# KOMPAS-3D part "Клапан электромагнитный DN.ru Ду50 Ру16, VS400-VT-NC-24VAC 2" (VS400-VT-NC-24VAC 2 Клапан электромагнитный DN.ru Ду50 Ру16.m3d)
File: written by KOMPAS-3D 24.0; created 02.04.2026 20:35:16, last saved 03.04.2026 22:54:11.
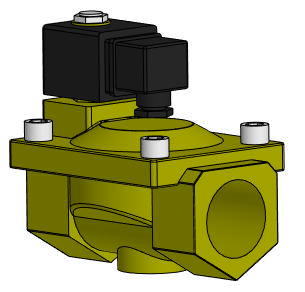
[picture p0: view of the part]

Document properties: Автор: artio; Полное имя файла: C:\Users\artio\OneDrive\Рабочий стол\Клапан электромагнитный DN.ru\VS400-VT-NC\VS400-VT-NC-24VAC 2 Клапан электромагнитный DN.ru Ду50 Ру16.m3d

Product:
- Body: Тело 1  | qty 1
    Масса: 7.119215
- Part/product: Клапан электромагнитный DN.ru Ду50 Ру16  | designation VS400-VT-NC-24VAC 2
    Масса: 3.509
    Раздел спецификации: Прочие изделия
    Примечание: D130-05502
    additional columns: ef56311e-7521-43dc-8291-0e6108b3d81d; VS400-ET-NC-220VAC 2; artio; c; Шероховатость не задана; Да

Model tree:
1. Операция без истории:1

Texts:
  VS400-VT-NC-24VAC 2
